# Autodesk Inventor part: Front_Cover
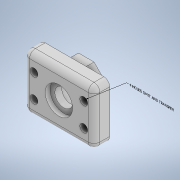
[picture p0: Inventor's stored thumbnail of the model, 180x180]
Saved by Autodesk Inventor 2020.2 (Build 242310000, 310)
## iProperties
Created: 2019-12
Part Number: Front_Cover
Material: Generic
Document SubType Name: Modeling
Designer: Patrick Everitt
Density: 1 g/cm^3
Appearance: Default
Description: 3.5x1.75 CRS 4.5 Lg
Author: Patrick Everitt
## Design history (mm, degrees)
node "Annotations"
  node "Leader Text 1"
sketch "Sketch1"
  geometry: L1 (-47.625, -44.45)-(47.625, -44.45); L2 (-57.15, -44.45)-(38.1, -44.45); L3 (57.15, -34.925)-(57.15, 34.925); L4 (47.625, 44.45)-(-47.625, 44.45); L5 (-57.15, 34.925)-(-57.15, -34.925); C1 r 14.478 at (0, 0); A1 r 9.525 centre (-47.625, -34.925) between (-57.15, -34.925) and (-47.625, -44.45); A2 r 9.525 centre (47.625, -34.925) between (47.625, -44.45) and (57.15, -34.925); A3 r 9.525 centre (47.625, 34.925) between (57.15, 34.925) and (47.625, 44.45); A4 r 9.525 centre (-47.625, 34.925) between (-47.625, 44.45) and (-57.15, 34.925); 4 further points
  constraints: 10 end point, 8 point on circle, 8 point on line, 8 tangent, 5 centre point, 3 equal radius, 2 horizontal, 2 perpendicular, 1 coincident, 1 collinear
  dimensions: "d0" = 114.3 distance of L2.start point (57.15, -44.45); "d2" = 88.9 distance of point (57.15, -44.45) point (57.15, 44.45); "d3" = 90 deg angle of L3 L1 (derived); "d4" = 114.3 distance of point (57.15, 44.45) point (-57.15, 44.45); "d5" = 90 deg angle of L4 L3 (derived); "d7" = 90 deg angle of L5 L4 (derived); "d8" = 57.15 distance from line of point (0, 0) L3 (= 0.5 x d0); "d9" = 44.45 distance from line of point (0, 0) L4 (= 0.5 x d2); "d10" = 9.525 radius of A1; "d11" = 28.956 diameter of C1
extrude "Extrusion1" new body sketch "Sketch1" distance "d12" = 25.4; taper "d13" = 0 deg
sketch "Sketch2"
  geometry: L1 (-25.4, -25.4)-(-25.4, 25.4); L2 (-12.7, 38.1)-(12.7, 38.1); L3 (25.4, 25.4)-(25.4, -25.4); L4 (12.7, -38.1)-(-12.7, -38.1); L5 (-25.4, 25.4)-(-12.7, 38.1); L6 (12.7, 38.1)-(25.4, 25.4); L7 (25.4, -25.4)-(12.7, -38.1); L8 (-12.7, -38.1)-(-25.4, -25.4); 5 further points
  constraints: 16 end point, 8 point on line, 3 perpendicular, 1 vertical
  dimensions: "d14" = 76.2 distance of point (-25.4, -38.1) point (-25.4, 38.1); "d15" = 50.8 distance of point (-25.4, 38.1) point (25.4, 38.1); "d16" = 12.7 distance of L1.end point (-25.4, 38.1); "d17" = 12.7 distance of L2.start point (-25.4, 38.1) (= d16); "d18" = 12.7 distance of L2.end point (25.4, 38.1) (= d16); "d19" = 12.7 distance of L3.start point (25.4, 38.1) (= d18); "d20" = 12.7 distance of L3.end point (25.4, -38.1) (= d16); "d21" = 12.7 distance of L4.start point (25.4, -38.1) (= d20); "d22" = 12.7 distance of L4.end point (-25.4, -38.1) (= d16); "d23" = 12.7 distance of L1.start point (-25.4, -38.1) (= d22); "d26" = 38.1 distance from line of L2 point (0, 0) (= 0.5 x d14); "d27" = 25.4 distance from line of L3 point (0, 0) (= 0.5 x d15)
extrude "Extrusion2" join sketch "Sketch2" distance "d28" = 19.05; taper "d29" = 0 deg
sketch "Sketch3"
  geometry: C1 r 17.463 at (0, 0); 1 further point
  constraints: 1 centre point, 1 coincident
  dimensions: "d30" = 34.925 diameter of C1
extrude "Extrusion3" cut sketch "Sketch3" distance "d31" = 25.4; taper "d32" = 0 deg
sketch "Sketch4"
  geometry: C1 r 22.225 at (0, 0); 1 further point
  constraints: 1 centre point, 1 coincident
  dimensions: "d33" = 44.45 diameter of C1
extrude "Extrusion4" cut sketch "Sketch4" distance "d34" = 7.9375; taper "d35" = 0 deg
fillet "Fillet1" dims "d36" = 9.525
sketch "Sketch5"
  geometry: 5 further points
  dimensions: "d44" = 19.05 vertical distance of point (0, 0) point (-40.488, 19.05); "d45" = 19.05 vertical distance of point (40.488, 19.05) point (0, 0) (= d44); "d46" = 19.05 vertical distance of point (40.488, -19.05) point (0, 0) (= d44); "d47" = 19.05 vertical distance of point (-40.488, -19.05) point (0, 0) (= d44); "d48" = 40.4876 horizontal distance of point (-40.488, 19.05) point (0, 0); "d49" = 40.4876 horizontal distance of point (40.488, 19.05) point (0, 0) (= d48); "d50" = 40.4876 horizontal distance of point (40.488, -19.05) point (0, 0) (= d49); "d51" = 40.4876 horizontal distance of point (-40.488, -19.05) point (0, 0) (= d48)
hole "Hole1" sketch "Sketch5" at (-40.488, -19.05), (-40.488, 19.05), (40.488, 19.05), (40.488, -19.05) diameter "d37" = 8.7376; stored, may be unused: countersink angle "d41" = 82 deg, drill point angle "d43" = 118 deg; dims "d38" = 19.05, "d39" = 12.7, "d40" = 8.3312, "d42" = 25.4
body "Solid1"
other parameters: "d52" = 53.85587 (derived)
